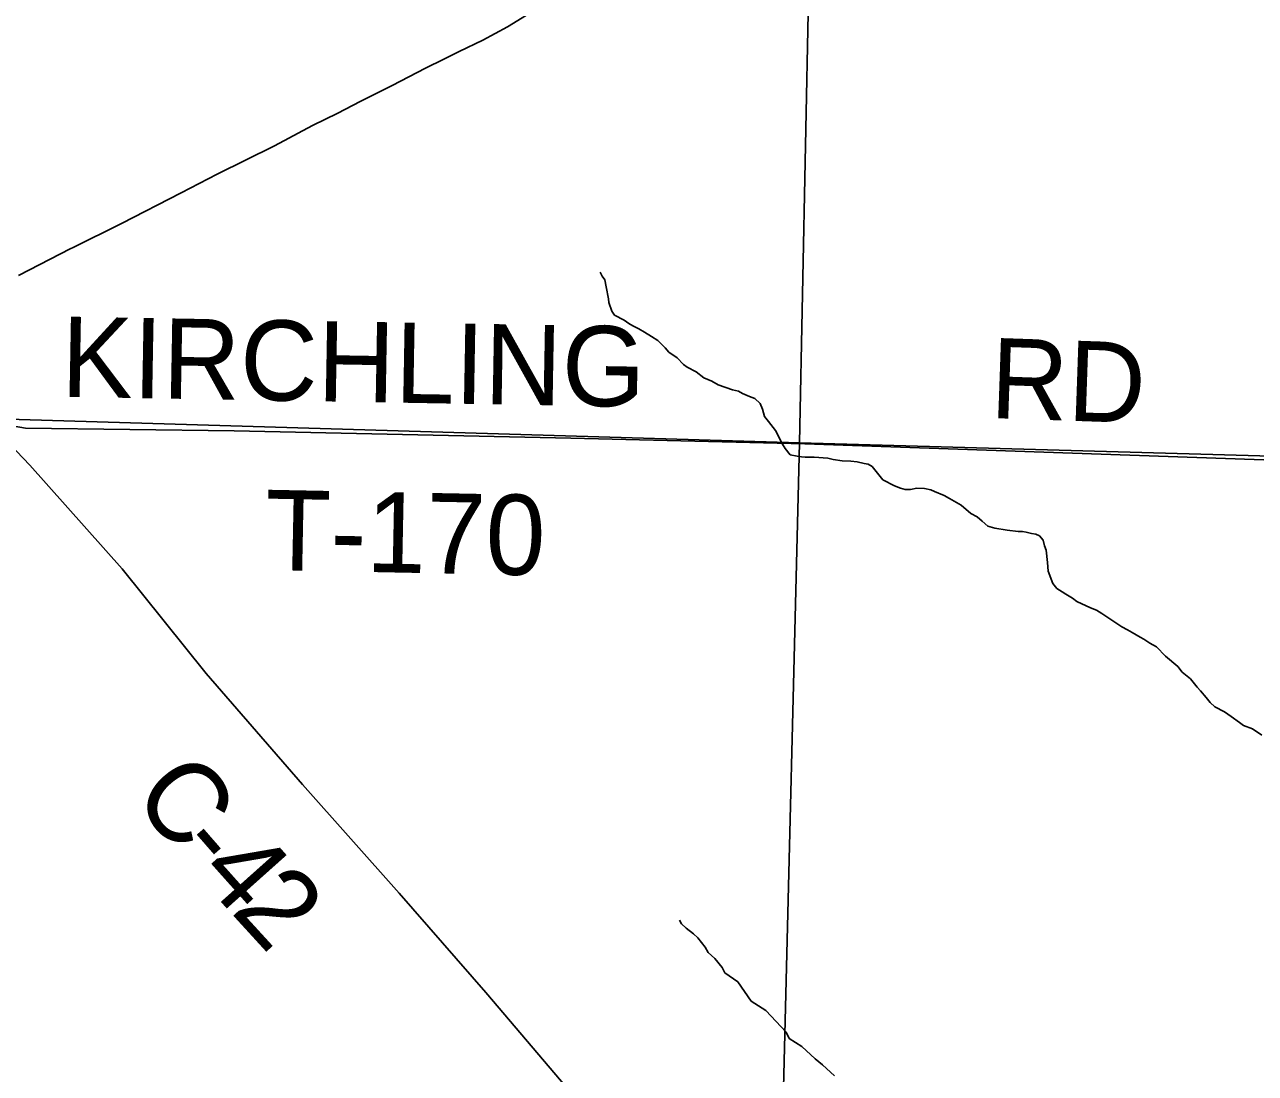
# Model space of a CAD drawing. Extents: x 0 to 34, y -2.3 to 22.
# Drawn here: x 3.017 to 3.889, y 17.952 to 18.694 of the extents above; entities that cross this region are included whole.
import ezdxf

# ---------------------------------------------------------------- set-up
doc = ezdxf.new("R2010")
doc.units = 0
for name, color, linetype in [('GM_X_County_Road', 7, 'Continuous'), ('GM_X_County_Road_Text', 7, 'Continuous'), ('GM_X_Minor_River', 7, 'Continuous'), ('GM_X_Section', 7, 'Continuous'), ('GM_X_State_Route', 7, 'Continuous'), ('GM_X_Township_Road', 7, 'Continuous'), ('GM_X_Township_Road_Text', 7, 'Continuous')]:
    doc.layers.add(name, color=color, linetype=linetype)

msp = doc.modelspace()

# ---------------------------------------------------------------- linework, layer by layer
at = {"layer": 'GM_X_County_Road'}
for p, q in [((2.99149, 18.41319), (3.02067, 18.38267)), ((3.02067, 18.38267), (3.08614, 18.30912)), ((3.08614, 18.30912), (3.14569, 18.23507)), ((3.14569, 18.23507), (3.21382, 18.15654)), ((3.21382, 18.15654), (3.28238, 18.07951)), ((3.28238, 18.07951), (3.3436, 18.00922)), ((3.3436, 18.00922), (3.46227, 17.8699))]:
    msp.add_line(p, q, dxfattribs=at)
at = {"layer": 'GM_X_Minor_River'}
for p, q in [((3.42614, 18.51645), (3.4247, 18.51915)), ((3.42796, 18.51374), (3.42614, 18.51645)), ((3.42896, 18.50877), (3.42796, 18.51374)), ((3.43062, 18.50036), (3.42896, 18.50877)), ((3.43092, 18.4977), (3.43062, 18.50036)), ((3.43302, 18.49155), (3.43092, 18.4977)), ((3.43484, 18.48884), (3.43302, 18.49155)), ((3.44158, 18.48522), (3.43484, 18.48884)), ((3.44493, 18.48285), (3.44158, 18.48522)), ((3.44793, 18.48124), (3.44493, 18.48285)), ((3.45205, 18.47921), (3.44793, 18.48124)), ((3.45616, 18.47681), (3.45205, 18.47921)), ((3.46101, 18.47363), (3.45616, 18.47681)), ((3.46549, 18.47084), (3.46101, 18.47363)), ((3.47067, 18.46575), (3.46549, 18.47084)), ((3.47324, 18.46263), (3.47067, 18.46575)), ((3.4792, 18.45866), (3.47324, 18.46263)), ((3.48363, 18.45397), (3.4792, 18.45866)), ((3.48623, 18.45199), (3.48363, 18.45397)), ((3.4926, 18.44876), (3.48623, 18.45199)), ((3.49818, 18.44442), (3.4926, 18.44876)), ((3.50381, 18.44197), (3.49818, 18.44442)), ((3.5083, 18.43956), (3.50381, 18.44197)), ((3.51845, 18.43584), (3.5083, 18.43956)), ((3.52261, 18.43495), (3.51845, 18.43584)), ((3.5256, 18.43335), (3.52261, 18.43495)), ((3.53049, 18.4313), (3.5256, 18.43335)), ((3.53424, 18.42967), (3.53049, 18.4313)), ((3.53794, 18.42614), (3.53424, 18.42967)), ((3.53973, 18.42229), (3.53794, 18.42614)), ((3.54109, 18.41693), (3.53973, 18.42229)), ((3.54403, 18.41343), (3.54109, 18.41693)), ((3.54879, 18.40721), (3.54403, 18.41343)), ((3.55383, 18.39756), (3.54879, 18.40721)), ((3.55564, 18.39447), (3.55383, 18.39756)), ((3.55931, 18.3898), (3.55564, 18.39447)), ((3.56422, 18.3889), (3.55931, 18.3898)), ((3.56725, 18.38842), (3.56422, 18.3889)), ((3.56991, 18.38835), (3.56725, 18.38842)), ((3.57637, 18.38816), (3.56991, 18.38835)), ((3.58585, 18.38749), (3.57637, 18.38816)), ((3.58963, 18.38662), (3.58585, 18.38749)), ((3.59606, 18.38567), (3.58963, 18.38662)), ((3.60214, 18.38549), (3.59606, 18.38567)), ((3.60668, 18.38498), (3.60214, 18.38549)), ((3.61159, 18.38369), (3.60668, 18.38498)), ((3.61462, 18.38322), (3.61159, 18.38369)), ((3.61723, 18.38162), (3.61462, 18.38322)), ((3.622, 18.37578), (3.61723, 18.38162)), ((3.62494, 18.37228), (3.622, 18.37578)), ((3.63318, 18.36785), (3.62494, 18.37228)), ((3.63731, 18.36621), (3.63318, 18.36785)), ((3.64071, 18.36535), (3.63731, 18.36621)), ((3.6445, 18.36524), (3.64071, 18.36535)), ((3.6491, 18.36624), (3.6445, 18.36524)), ((3.65441, 18.36608), (3.6491, 18.36624)), ((3.65895, 18.36519), (3.65441, 18.36608)), ((3.66157, 18.36397), (3.65895, 18.36519)), ((3.66833, 18.36111), (3.66157, 18.36397)), ((3.67208, 18.3591), (3.66833, 18.36111)), ((3.6803, 18.3543), (3.67208, 18.3591)), ((3.68735, 18.34839), (3.6803, 18.3543)), ((3.69184, 18.34598), (3.68735, 18.34839)), ((3.69517, 18.34284), (3.69184, 18.34598)), ((3.69925, 18.3393), (3.69517, 18.34284)), ((3.70415, 18.33801), (3.69925, 18.3393)), ((3.71286, 18.33661), (3.70415, 18.33801)), ((3.72081, 18.33562), (3.71286, 18.33661)), ((3.72385, 18.33553), (3.72081, 18.33562)), ((3.7265, 18.33507), (3.72385, 18.33553)), ((3.73027, 18.3342), (3.7265, 18.33507)), ((3.7333, 18.33373), (3.73027, 18.3342)), ((3.73593, 18.33251), (3.7333, 18.33373)), ((3.7385, 18.32939), (3.73593, 18.33251)), ((3.73953, 18.32557), (3.7385, 18.32939)), ((3.74058, 18.3225), (3.73953, 18.32557)), ((3.74146, 18.31373), (3.74058, 18.3225)), ((3.74204, 18.30764), (3.74146, 18.31373)), ((3.74521, 18.29881), (3.74204, 18.30764)), ((3.74815, 18.2953), (3.74521, 18.29881)), ((3.75188, 18.29291), (3.74815, 18.2953)), ((3.75449, 18.29131), (3.75188, 18.29291)), ((3.75935, 18.28851), (3.75449, 18.29131)), ((3.76232, 18.28614), (3.75935, 18.28851)), ((3.77208, 18.28167), (3.76232, 18.28614)), ((3.77621, 18.28003), (3.77208, 18.28167)), ((3.77994, 18.27764), (3.77621, 18.28003)), ((3.79411, 18.2681), (3.77994, 18.27764)), ((3.79823, 18.26608), (3.79411, 18.2681)), ((3.8016, 18.26408), (3.79823, 18.26608)), ((3.8072, 18.26088), (3.8016, 18.26408)), ((3.80982, 18.25928), (3.8072, 18.26088)), ((3.81392, 18.2565), (3.80982, 18.25928)), ((3.81879, 18.25407), (3.81392, 18.2565)), ((3.82506, 18.24743), (3.81879, 18.25407)), ((3.83396, 18.23995), (3.82506, 18.24743)), ((3.83689, 18.23606), (3.83396, 18.23995)), ((3.84283, 18.23132), (3.83689, 18.23606)), ((3.84761, 18.22548), (3.84283, 18.23132)), ((3.84981, 18.22276), (3.84761, 18.22548)), ((3.85385, 18.21808), (3.84981, 18.22276)), ((3.85679, 18.21457), (3.85385, 18.21808)), ((3.86012, 18.21144), (3.85679, 18.21457)), ((3.86686, 18.20782), (3.86012, 18.21144)), ((3.87171, 18.20463), (3.86686, 18.20782)), ((3.87766, 18.20028), (3.87171, 18.20463)), ((3.88027, 18.1983), (3.87766, 18.20028)), ((3.88666, 18.19583), (3.88027, 18.1983)), ((3.89337, 18.19145), (3.88666, 18.19583)), ((3.48234, 18.05783), (3.48089, 18.06053)), ((3.48567, 18.05469), (3.48234, 18.05783)), ((3.49088, 18.05074), (3.48567, 18.05469)), ((3.49384, 18.04799), (3.49088, 18.05074)), ((3.49896, 18.04138), (3.49384, 18.04799)), ((3.50113, 18.03752), (3.49896, 18.04138)), ((3.50595, 18.03319), (3.50113, 18.03752)), ((3.51109, 18.02696), (3.50595, 18.03319)), ((3.51288, 18.02311), (3.51109, 18.02696)), ((3.5222, 18.01676), (3.51288, 18.02311)), ((3.53168, 18.00318), (3.5222, 18.01676)), ((3.54213, 17.99641), (3.53168, 18.00318)), ((3.55651, 17.98117), (3.54213, 17.99641)), ((3.55866, 17.97655), (3.55651, 17.98117)), ((3.56762, 17.97096), (3.55866, 17.97655)), ((3.57687, 17.96233), (3.56762, 17.97096)), ((3.58207, 17.958), (3.57687, 17.96233)), ((3.59058, 17.95015), (3.58207, 17.958))]:
    msp.add_line(p, q, dxfattribs=at)
at = {"layer": 'GM_X_Section'}
for p, q in [((3.58614, 19.40211), (3.56585, 18.39828)), ((3.56585, 18.39828), (3.58614, 19.40211)), ((3.56585, 18.39828), (2.55547, 18.42887)), ((2.55547, 18.42887), (3.56585, 18.39828)), ((3.56585, 18.39828), (3.54075, 17.39533)), ((3.54075, 17.39533), (3.56585, 18.39828)), ((4.3586, 18.376), (3.56585, 18.39828)), ((3.56585, 18.39828), (4.3586, 18.376))]:
    msp.add_line(p, q, dxfattribs=at)
at = {"layer": 'GM_X_State_Route'}
for p, q in [((3.35911, 18.6929), (3.38298, 18.70766)), ((3.34149, 18.68358), (3.35911, 18.6929)), ((3.32479, 18.67539), (3.34149, 18.68358)), ((3.31393, 18.67006), (3.32479, 18.67539)), ((3.30102, 18.66361), (3.31393, 18.67006)), ((3.27736, 18.65142), (3.30102, 18.66361)), ((3.25464, 18.63998), (3.27736, 18.65142)), ((3.23885, 18.63175), (3.25464, 18.63998)), ((3.22102, 18.62304), (3.23885, 18.63175)), ((3.19398, 18.6088), (3.22102, 18.62304)), ((3.15342, 18.58873), (3.19398, 18.6088)), ((3.1278, 18.5753), (3.15342, 18.58873)), ((3.08554, 18.55378), (3.1278, 18.5753)), ((3.05088, 18.53658), (3.08554, 18.55378)), ((3.01253, 18.51685), (3.04982, 18.53605)), ((3.04982, 18.53605), (3.05088, 18.53658))]:
    msp.add_line(p, q, dxfattribs=at)
at = {"layer": 'GM_X_Township_Road'}
for p, q in [((2.99149, 18.41319), (3.01772, 18.4087)), ((3.01772, 18.4087), (3.16537, 18.40694)), ((3.16537, 18.40694), (3.4039, 18.40176)), ((3.4039, 18.40176), (3.56975, 18.39759)), ((3.56975, 18.39759), (3.88784, 18.38653)), ((3.88784, 18.38653), (4.33164, 18.37486))]:
    msp.add_line(p, q, dxfattribs=at)

# ---------------------------------------------------------------- texts
at = {"layer": 'GM_X_County_Road_Text'}
for s, rotation, p in [('C', 310.42001, (3.09189, 18.14728)), ('-', 311.06779, (3.1226, 18.11122)), ('4', 311.74839, (3.13842, 18.09308)), ('2', 312.44208, (3.16223, 18.06641))]:
    msp.add_text(s, height=0.05682, rotation=rotation, dxfattribs=at).set_placement(p)
at = {"layer": 'GM_X_Township_Road_Text'}
for s, rotation, p in [('KIRCHLING', 358.99852, (3.04257, 18.43102)), ('RD', 358.02521, (3.70041, 18.416)), ('T-170', 358.87678, (3.18688, 18.3084))]:
    msp.add_text(s, height=0.056818, rotation=rotation, dxfattribs=at).set_placement(p)

doc.saveas('drawing.dxf')
